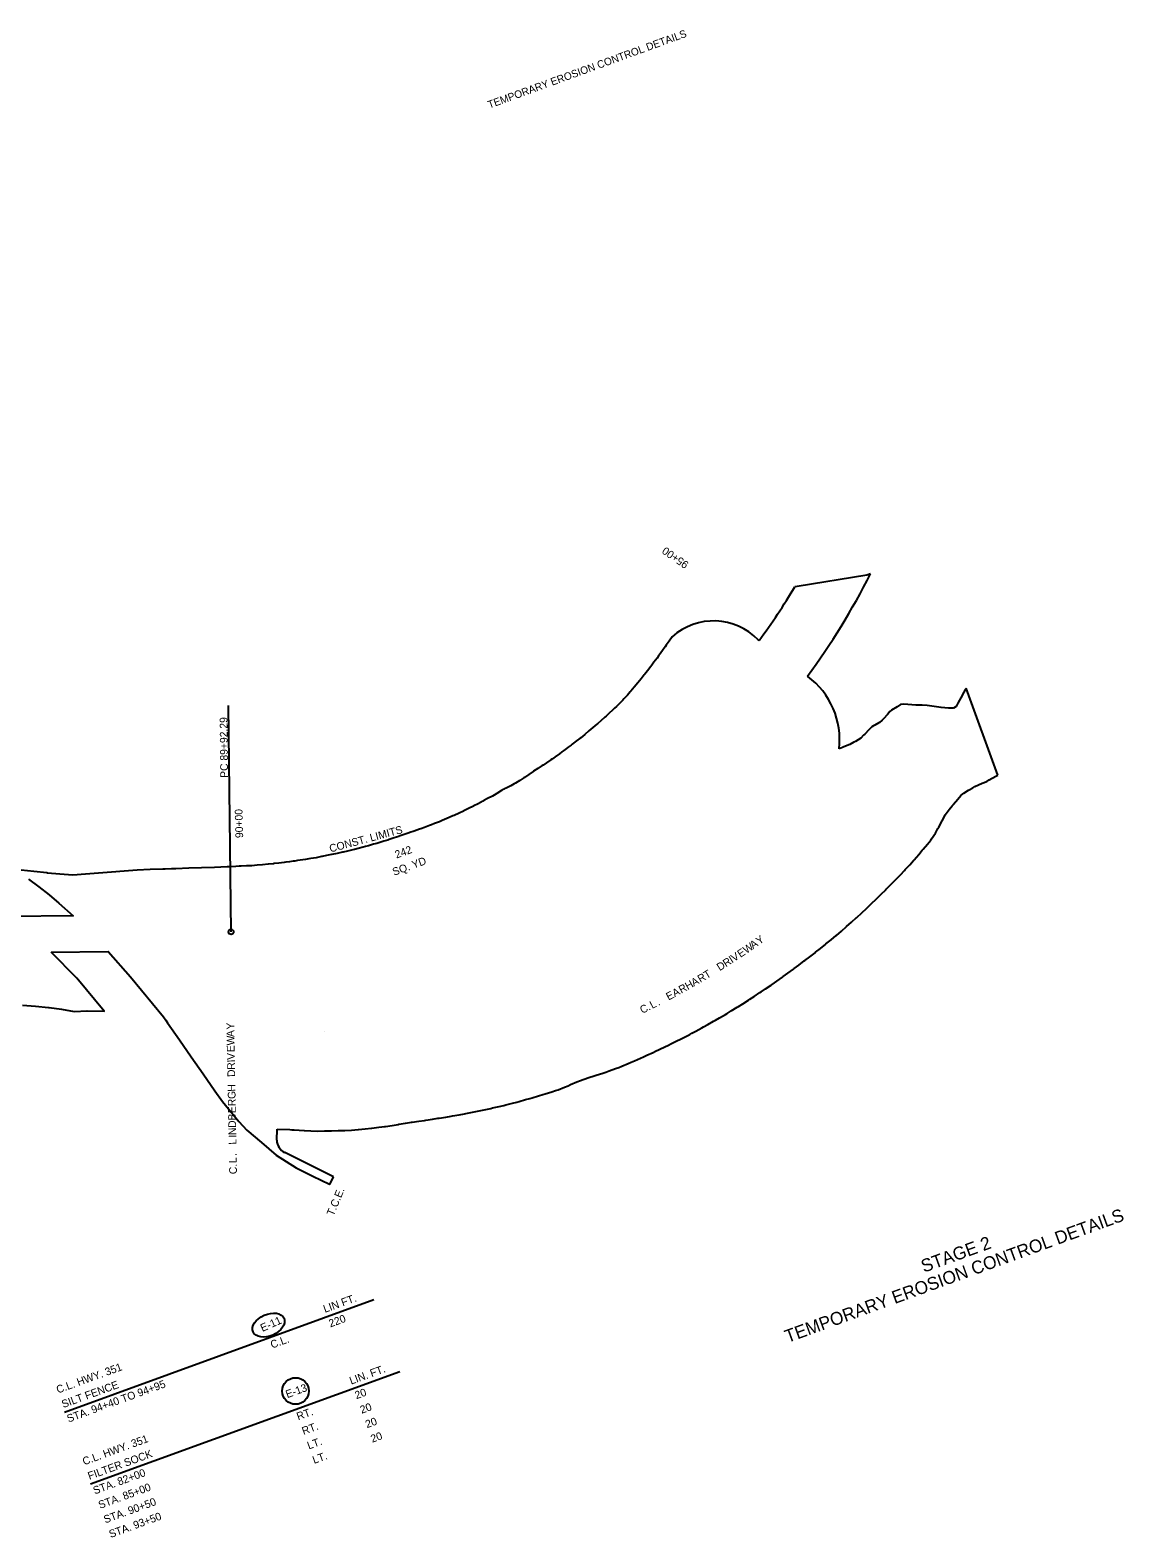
# Model space of a CAD drawing. Extents: x 1710803 to 1712425, y 548489 to 549912.
# Drawn here: x 1711577 to 1712425, y 548742 to 549912 of the extents above; entities that cross this region are included whole.
import ezdxf

# ---------------------------------------------------------------- set-up
doc = ezdxf.new("R2010")
doc.units = 0
for name, color, linetype in [('R_Contours', 7, 'Continuous'), ('R_Erosion', 7, 'Continuous'), ('R_Horz Alg', 7, 'Continuous'), ('R_Horz Alg Annot', 7, 'Continuous'), ('R_Proposed Const Limits_Cut', 7, 'Continuous')]:
    doc.layers.add(name, color=color, linetype=linetype)

msp = doc.modelspace()

# ---------------------------------------------------------------- linework, layer by layer
at = {"layer": 'R_Contours'}
for p, q in [((1711603.8, 548839.9), (1711843.6, 548927.1)), ((1711624, 548784.1), (1711863.9, 548871.4))]:
    msp.add_line(p, q, dxfattribs=at)
at = {"layer": 'R_Erosion'}
msp.add_circle((1711783, 548856.2), 10.3, dxfattribs=at)
msp.add_ellipse((1711762.1, 548907.3), major_axis=(12, 5.3), ratio=0.638788, dxfattribs=at)
at = {"layer": 'R_Horz Alg'}
for p, q in [((1712142.4, 549438.5), (1712141.8, 549438.9)), ((1712180.1, 549410.6), (1712179.9, 549410.8)), ((1712295.3, 549387.4), (1712293.1, 549386)), ((1711768.5, 549050.7), (1711768.8, 549059.4)), ((1711812.5, 549022.5), (1711774.6, 549041.3)), ((1711809.5, 549016.5), (1711812.5, 549022.5))]:
    msp.add_line(p, q, dxfattribs=at)
for points in [[(1712228.9, 549490.2), (1712226, 549489.2), (1712171.9, 549480.3), (1712170.2, 549480.2)], [(1712074.9, 549441.4), (1712072.7, 549438.1), (1712070.4, 549434.8), (1712069.5, 549433.6), (1712068, 549431.5), (1712065.7, 549428.2), (1712064.5, 549426.5), (1712063.3, 549424.9), (1712060.9, 549421.6), (1712059.2, 549419.4), (1712058.4, 549418.3), (1712056, 549415.1), (1712053.8, 549412.4), (1712053.4, 549411.9), (1712050.9, 549408.7), (1712048.3, 549405.6), (1712048.3, 549405.6), (1712045.6, 549402.4), (1712043, 549399.3), (1712042.5, 549398.8), (1712040.3, 549396.2), (1712037.6, 549393.2), (1712036.7, 549392.2)], [(1712302.9, 549401.6), (1712302.4, 549400.6), (1712301.2, 549398.4), (1712298.9, 549394.1), (1712297.9, 549392.1), (1712296.6, 549389.8), (1712295.3, 549387.4)], [(1712327.5, 549334), (1712302.9, 549401.6)], [(1712036.7, 549392.2), (1712034.7, 549390.2), (1712031.8, 549387.4), (1712030.4, 549386), (1712028.9, 549384.6), (1712025.9, 549381.8), (1712023.9, 549379.9), (1712022.9, 549379), (1712019.8, 549376.3), (1712017.3, 549374.1), (1712016.7, 549373.6), (1712013.6, 549370.9), (1712010.5, 549368.3), (1712010.5, 549368.3), (1712007.3, 549365.7), (1712004.1, 549363.1), (1712003.6, 549362.8), (1712000.9, 549360.6), (1711997.6, 549358.1), (1711996.6, 549357.4), (1711994.3, 549355.7), (1711993.1, 549354.7), (1711991, 549353.2), (1711989.5, 549352), (1711987.7, 549350.7), (1711984.4, 549348.3), (1711982.9, 549347.3), (1711982.3, 549346.8), (1711981, 549346), (1711977.7, 549343.6), (1711975, 549341.8), (1711974.2, 549341.4), (1711970.8, 549339.1), (1711967.5, 549337), (1711967.3, 549336.9), (1711963.9, 549334.6), (1711960.5, 549332.2), (1711960.1, 549332), (1711957, 549330), (1711953.5, 549327.9), (1711952.5, 549327.3), (1711950, 549325.8), (1711946.3, 549324), (1711945.4, 549323.6), (1711944.6, 549323.1), (1711942.6, 549322.1), (1711939.1, 549319.9), (1711937, 549318.6), (1711935.6, 549317.7), (1711931.9, 549315.8), (1711929.1, 549314.3), (1711928.3, 549313.8), (1711924.6, 549311.9), (1711921.2, 549310.1), (1711920.9, 549310), (1711917.2, 549308.1), (1711913.5, 549306.3), (1711913.2, 549306.1), (1711909.8, 549304.5), (1711906, 549302.8), (1711905, 549302.4), (1711902.2, 549301.1), (1711898.4, 549299.5), (1711896.8, 549298.8), (1711894.6, 549297.9), (1711890.7, 549296.4), (1711888.5, 549295.5), (1711886.8, 549294.9), (1711882.9, 549293.5), (1711880.1, 549292.4), (1711879, 549292.1), (1711875.1, 549290.7), (1711871.6, 549289.6), (1711871.2, 549289.4), (1711867.3, 549288), (1711863.3, 549286.6), (1711863.1, 549286.5), (1711859.4, 549285.3), (1711855.5, 549284), (1711854.6, 549283.7), (1711851.5, 549282.7), (1711847.5, 549281.5), (1711846, 549281.1), (1711843.5, 549280.4), (1711839.5, 549279.2), (1711837.3, 549278.7), (1711835.5, 549278.2), (1711831.5, 549277.1), (1711828.6, 549276.4), (1711827.4, 549276.1), (1711823.4, 549275.1), (1711819.8, 549274.3), (1711819.3, 549274.2), (1711815.2, 549273.3), (1711811.2, 549272.4), (1711811, 549272.4), (1711807.1, 549271.6), (1711803.6, 549270.9), (1711803, 549270.8), (1711802.2, 549270.6), (1711798.9, 549270), (1711794.8, 549269.3), (1711793.3, 549269.1), (1711790.7, 549268.6), (1711786.5, 549268), (1711784.4, 549267.7), (1711782.4, 549267.4), (1711781.1, 549267.2), (1711778.3, 549266.8), (1711775.4, 549266.4), (1711774.1, 549266.3), (1711770, 549265.8), (1711766.5, 549265.4), (1711766.4, 549265.4), (1711765.8, 549265.3), (1711762, 549264.9), (1711761.7, 549264.9), (1711757.5, 549264.5), (1711757.5, 549264.5), (1711753.3, 549264.1), (1711749.1, 549263.8), (1711748.4, 549263.8), (1711745, 549263.6), (1711740.8, 549263.3), (1711739.4, 549263.3), (1711736.6, 549263.2), (1711732.4, 549263), (1711730.1, 549262.9), (1711720.1, 549262.5), (1711710.1, 549262.1), (1711700.2, 549261.8), (1711690.2, 549261.4), (1711686.8, 549261.3), (1711681.9, 549261.1), (1711680.2, 549261.1), (1711670.2, 549260.8), (1711660.2, 549260.4), (1711650.2, 549259.6), (1711640.2, 549258.8), (1711630.2, 549257.9), (1711620.2, 549257.3), (1711610.2, 549256.5), (1711600.2, 549257.1), (1711590.8, 549258.1), (1711590.2, 549258.2), (1711580.2, 549259.3), (1711570.2, 549260.4)], [(1712293.1, 549386), (1712289.4, 549386.1), (1712283.6, 549386.6), (1712272.7, 549388.1), (1712268.8, 549388.4), (1712264.5, 549388.4), (1712263.9, 549388.4), (1712254.7, 549389.1), (1712252, 549388.8), (1712249.4, 549387.1), (1712245.2, 549384.5), (1712243.9, 549383.4), (1712241.9, 549381.2), (1712238.8, 549377.8), (1712237.8, 549376.6), (1712235.7, 549375), (1712235.3, 549374.7), (1712232.1, 549372.8), (1712231.1, 549372.2), (1712229.8, 549371.4), (1712229.8, 549371.4), (1712227.6, 549369.2), (1712224.4, 549365.9), (1712224.3, 549365.8), (1712223.5, 549365), (1712221.2, 549362.7), (1712217.1, 549360.2), (1712216, 549359.5), (1712212.8, 549357.9), (1712208.2, 549355.9), (1712207.1, 549355.4), (1712204.5, 549354.4)], [(1711768.8, 549059.4), (1711778.6, 549059), (1711780, 549058.9), (1711782, 549058.8), (1711789.6, 549058.4), (1711790, 549058.4), (1711794.9, 549058.1), (1711800.2, 549057.9), (1711800.4, 549057.9), (1711805.4, 549058), (1711810.7, 549058), (1711810.8, 549058), (1711816, 549058.2), (1711821.2, 549058.4), (1711821.2, 549058.4), (1711826.5, 549058.7), (1711831.6, 549059.2), (1711831.8, 549059.2), (1711837, 549059.7), (1711842, 549060.2), (1711842.2, 549060.2), (1711847.5, 549060.8), (1711852.3, 549061.5), (1711852.7, 549061.5), (1711857.9, 549062.3), (1711862.6, 549063.1), (1711863.1, 549063.2), (1711868.3, 549064.1), (1711872.8, 549064.8), (1711873.5, 549064.9), (1711878.7, 549065.6), (1711883.1, 549066.2), (1711883.9, 549066.4), (1711889.1, 549067.1), (1711893.4, 549067.8), (1711894.4, 549067.9), (1711899.6, 549068.7), (1711903.7, 549069.4), (1711904.8, 549069.6), (1711909.9, 549070.5), (1711914, 549071.2), (1711915.1, 549071.5), (1711920.3, 549072.5), (1711924.2, 549073.3), (1711925.5, 549073.5), (1711930.6, 549074.6), (1711934.4, 549075.4), (1711935.8, 549075.8), (1711940.9, 549077), (1711944.5, 549077.8), (1711946.1, 549078.2), (1711951.2, 549079.5), (1711954.6, 549080.4), (1711956.3, 549080.9), (1711961.3, 549082.3), (1711964.7, 549083.2), (1711966.4, 549083.7), (1711971.5, 549085.2), (1711974.7, 549086.2), (1711976.5, 549086.8), (1711981.6, 549088.3), (1711984.6, 549089.3), (1711986.6, 549090), (1711991.5, 549091.9), (1711994.3, 549093.1), (1711996.3, 549094), (1712001.2, 549096), (1712004, 549097.1), (1712006.1, 549097.9), (1712011.1, 549099.7), (1712013.8, 549100.5), (1712016.2, 549101.2), (1712021.2, 549102.8), (1712023.7, 549103.7), (1712026.2, 549104.5), (1712031.2, 549106.3), (1712033.6, 549107.2), (1712036.1, 549108.2), (1712040.9, 549110.3), (1712043.2, 549111.3), (1712045.8, 549112.4), (1712050.6, 549114.5), (1712052.7, 549115.5), (1712055.4, 549116.7), (1712060.2, 549118.9), (1712062.2, 549119.8), (1712065, 549121.2), (1712069.8, 549123.5), (1712071.6, 549124.4), (1712074.5, 549125.8), (1712079.2, 549128.2), (1712080.9, 549129), (1712084, 549130.5), (1712088.7, 549132.9), (1712090.2, 549133.8), (1712093.3, 549135.4), (1712098, 549137.9), (1712099.4, 549138.7), (1712102.6, 549140.5), (1712107.2, 549143.1), (1712108.5, 549143.8), (1712111.8, 549145.7), (1712116.3, 549148.4), (1712117.6, 549149.1), (1712120.9, 549151.1), (1712125.4, 549153.9), (1712126.4, 549154.6), (1712129.8, 549156.7), (1712134.3, 549159.5), (1712135.3, 549160.2), (1712138.7, 549162.4), (1712143.1, 549165.3), (1712144, 549165.9), (1712147.5, 549168.2), (1712151.9, 549171.2), (1712152.6, 549171.7), (1712156.2, 549174.3), (1712160.5, 549177.3), (1712161.2, 549177.7), (1712164.8, 549180.4), (1712169.1, 549183.5), (1712169.6, 549183.9), (1712173.3, 549186.7), (1712177.5, 549189.9), (1712177.9, 549190.2), (1712181.7, 549193.1), (1712185.9, 549196.3), (1712186.2, 549196.6), (1712190, 549199.6), (1712194.1, 549202.9), (1712194.3, 549203.1), (1712198.2, 549206.3), (1712202.3, 549209.6), (1712202.4, 549209.7), (1712206.3, 549213.1), (1712210.3, 549216.5), (1712210.3, 549216.5), (1712214.2, 549220), (1712218, 549223.5), (1712218.1, 549223.6), (1712222, 549227.2), (1712225.7, 549230.6), (1712225.9, 549230.8), (1712229.7, 549234.4), (1712233.2, 549237.8), (1712233.5, 549238.1), (1712237.2, 549241.8), (1712240.6, 549245.1), (1712241, 549245.5), (1712244.7, 549249.2), (1712247.9, 549252.6), (1712248.4, 549253), (1712252, 549256.8), (1712255.1, 549260.1), (1712255.6, 549260.7), (1712259.2, 549264.5), (1712262.1, 549267.8), (1712262.7, 549268.4), (1712266.2, 549272.4), (1712268.9, 549275.7), (1712269.6, 549276.5), (1712272.9, 549280.5), (1712275.5, 549283.7), (1712276.2, 549284.6), (1712279.2, 549289), (1712281.1, 549292.6), (1712281.8, 549293.8), (1712284.3, 549298.5), (1712286.2, 549301.9), (1712286.8, 549303.2), (1712289.9, 549307.5), (1712292.2, 549310.3), (1712293.1, 549311.3), (1712293.2, 549311.5), (1712296.5, 549315.5), (1712298.8, 549318.3), (1712298.8, 549318.3), (1712300.1, 549319.4), (1712301.1, 549320.1), (1712304.8, 549322.4), (1712305.2, 549322.7), (1712308.1, 549324.3), (1712309.8, 549325.2), (1712315.3, 549327.8), (1712319.1, 549329.2), (1712320.9, 549330.3), (1712326, 549333.2), (1712327.5, 549334)], [(1711576, 549253.3), (1711584, 549247.3), (1711592, 549241.3), (1711599.5, 549234.7), (1711610.6, 549225), (1711560.7, 549224.4)], [(1711593.5, 549196.8), (1711637.6, 549197.3), (1711655.1, 549177.5), (1711680.5, 549146.5), (1711682.4, 549143.9), (1711683.7, 549141.8), (1711692.9, 549128.6), (1711702.1, 549115.5), (1711711.3, 549102.3), (1711720.5, 549089.1), (1711726.3, 549080.9), (1711739, 549065.4), (1711745.2, 549058.5), (1711756.6, 549048.9), (1711768, 549039.3), (1711783.6, 549029.4), (1711796.4, 549023), (1711809.2, 549016.7), (1711809.5, 549016.5)], [(1711621.4, 549151.2), (1711634.7, 549150.9), (1711613.5, 549176.4), (1711593.5, 549196.8)], [(1711571.3, 549155.5), (1711581.3, 549154.7), (1711591.4, 549153.7), (1711591.9, 549153.7), (1711601.4, 549152.4), (1711611.4, 549150.7), (1711621.4, 549151.2)]]:
    msp.add_lwpolyline(points, dxfattribs=at)
for centre, radius, start, end in [((1711727, 549745.3), 563, 323.5493, 333.0539), ((1711727, 549745.3), 516.4, 323.5492, 329.11), ((1712107.1, 549405.4), 48.3, 44.026, 131.674), ((1712143.9, 549361.5), 61, 353.3207, 53.5498), ((1711779.5, 549051.2), 11.1, 182.4595, 243.5578)]:
    msp.add_arc(centre, radius, start, end, dxfattribs=at)
at = {"layer": 'R_Horz Alg Annot'}
msp.add_line((1711805.5, 549135.2), (1711805.4, 549135.2), dxfattribs=at)
msp.add_lwpolyline([(1711733, 549212.4), (1711731.1, 549388.2)], dxfattribs=at)
msp.add_circle((1711733, 549212.4), 2, dxfattribs=at)
at = {"layer": 'R_Proposed Const Limits_Cut'}
msp.add_lwpolyline([(1711621.1, 549150.8), (1711620.9, 549151.2)], dxfattribs=at)

# ---------------------------------------------------------------- texts
at = {"layer": 'R_Contours'}
for s, height, rotation, p in [('CONST. LIMITS', 6, 15.075, (1711810.1, 549274)), ('242 ', 6, 20, (1711861.3, 549269.3)), ('SQ. YD', 6, 20, (1711859.4, 549255.9)), ('Y', 6, 35.4733, (1712142.6, 549202.2)), ('E', 6, 33.8756, (1712128, 549192.2)), ('W', 6, 34.3626, (1712132.5, 549195.2)), ('A', 6, 34.9436, (1712137.8, 549198.9)), ('D', 6, 32.1411, (1712111.9, 549181.9)), ('R', 6, 32.6538, (1712116.7, 549184.9)), ('I', 6, 33.1664, (1712121.4, 549187.9)), ('V', 6, 33.3458, (1712123.1, 549189)), ('H', 6, 29.5394, (1712087.1, 549167.2)), ('A', 6, 30.0264, (1712091.8, 549169.9)), ('R', 6, 30.5562, (1712096.9, 549172.8)), ('T', 6, 31.0688, (1712101.7, 549175.7)), ('E', 6, 28.01, (1712072.2, 549159.1)), ('A', 6, 28.497, (1712077, 549161.7)), ('R', 6, 29.0267, (1712082.1, 549164.5)), ('C', 6, 25.938, (1712051.8, 549148.8)), ('.', 6, 26.4507, (1712056.9, 549151.3)), ('L', 6, 26.7155, (1712059.5, 549152.6)), ('.', 6, 27.2026, (1712064.3, 549155)), ('Y', 6, 91.0787, (1711735.5, 549136.7)), ('A', 6, 91.0787, (1711735.6, 549130.9)), ('W', 6, 91.0787, (1711735.7, 549124.4)), ('E', 6, 91.0787, (1711735.8, 549119.1)), ('V', 6, 91.0787, (1711735.9, 549113.2)), ('I', 6, 91.0787, (1711736, 549111.2)), ('R', 6, 91.0787, (1711736.1, 549105.5)), ('D', 6, 91.0787, (1711736.2, 549099.9)), ('H', 6, 91.0787, (1711736.4, 549088.5)), ('G', 6, 91.0787, (1711736.5, 549082.8)), ('R', 6, 91.0787, (1711736.6, 549077.2)), ('E', 6, 91.0787, (1711736.7, 549071.8)), ('B', 6, 91.0787, (1711736.8, 549066.1)), ('D', 6, 91.0787, (1711736.9, 549060.4)), ('N', 6, 91.0787, (1711737, 549054.8)), ('I', 6, 91.0787, (1711737.1, 549052.8)), ('L', 6, 91.0787, (1711737.2, 549047.4)), ('L', 6, 91.0787, (1711737.4, 549033.1)), ('.', 6, 91.0787, (1711737.3, 549038.5)), ('C', 6, 91.0787, (1711737.6, 549024.5)), ('.', 6, 91.0787, (1711737.5, 549030.2)), ('TEMPORARY EROSION CONTROL DETAILS', 10, 20, (1712164.5, 548893.4)), ('STAGE 2', 10, 20, (1712270.2, 548947.9)), ('LIN FT.', 6, 20, (1711805.8, 548916.8)), ('220', 6, 20, (1711810, 548905.5)), ('C.L.', 6, 20, (1711764.8, 548889.1)), ('C.L. HWY. 351', 6, 20, (1711598.8, 548854.2)), ('LIN. FT. ', 6, 20, (1711826.1, 548861.1)), ('SILT FENCE', 6, 20, (1711602.9, 548842.9)), ('STA. 94+40 TO 94+95', 6, 20, (1711607, 548831.7)), ('20', 6, 20, (1711830.2, 548849.8)), ('20', 6, 20, (1711834.3, 548838.5)), ('RT.', 6, 20, (1711785.1, 548833.4)), ('20', 6, 20, (1711838.4, 548827.3)), ('RT.', 6, 20, (1711789.2, 548822.1)), ('20', 6, 20, (1711842.5, 548816)), ('C.L. HWY. 351', 6, 20, (1711619.1, 548798.5)), ('LT.', 6, 20, (1711793.3, 548810.8)), ('FILTER SOCK', 6, 20, (1711623.2, 548787.2)), ('LT.', 6, 20, (1711797.4, 548799.6)), ('STA. 82+00', 6, 20, (1711627.3, 548775.9)), ('STA. 85+00', 6, 20, (1711631.4, 548764.7)), ('STA. 90+50', 6, 20, (1711635.5, 548753.4)), ('STA. 93+50', 6, 20, (1711639.6, 548742.1))]:
    msp.add_text(s, height=height, rotation=rotation, dxfattribs=at).set_placement(p)
at = {"layer": 'R_Erosion'}
for s, height, rotation, p in [('TEMPORARY EROSION CONTROL DETAILS', 5.862, 20, (1711933.3, 549851.2)), ('E-11', 6, 23.8359, (1711757.3, 548902)), ('E-13', 6, 20, (1711776.6, 548850.6))]:
    msp.add_text(s, height=height, rotation=rotation, dxfattribs=at).set_placement(p)
at = {"layer": 'R_Horz Alg Annot'}
for s, rotation, p in [('95+00', 145.2214, (1712088.4, 549498.7)), ('PC 89+92.29', 90.6428, (1711730.7, 549332)), ('90+00', 91.4714, (1711742.4, 549285.3)), ('T.C.E.', 67.2666, (1711812.4, 548991.6))]:
    msp.add_text(s, height=6, rotation=rotation, dxfattribs=at).set_placement(p)

doc.saveas('drawing.dxf')
